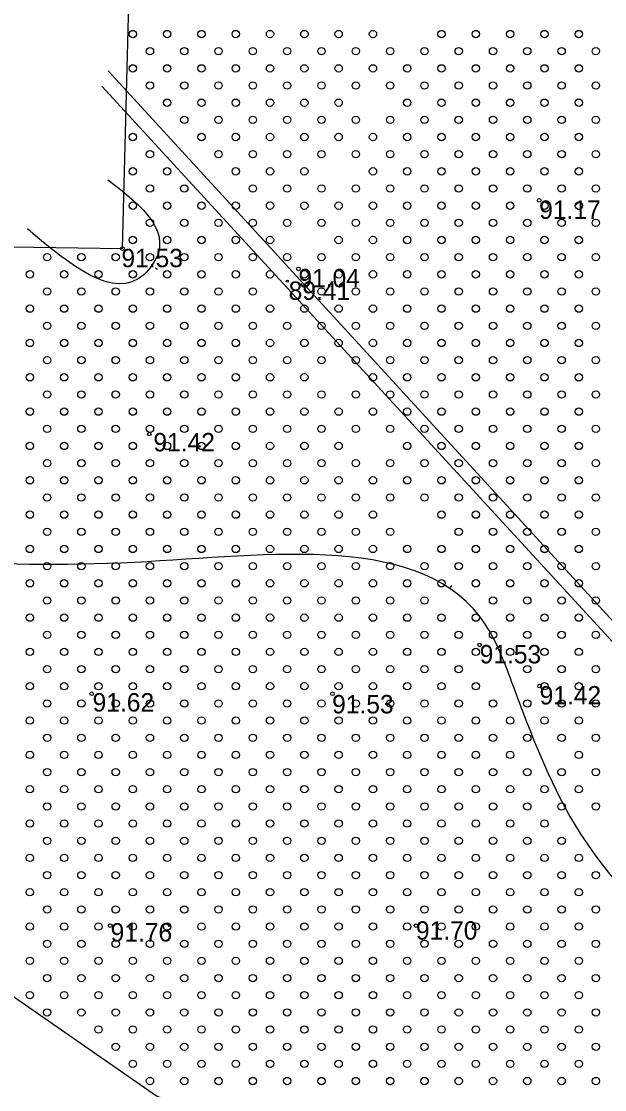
# Model space of a CAD drawing. Extents: x 316000 to 728450, y 314368 to 726000.
# Drawn here: x 725534.2 to 725653.3, y 315232.8 to 315450.6 of the extents above; entities that cross this region are included whole.
import ezdxf

# ---------------------------------------------------------------- set-up
doc = ezdxf.new("R2010")
doc.units = 0
for name, color, linetype in [('HIDG_ELEM_####_####_#', 7, 'Continuous'), ('HIDG_GRAV_####_####_#', 7, 'Continuous'), ('RAMI_UZMR_####_####_#', 7, 'Continuous'), ('RELJ_AATZ_####_TKST_#', 7, 'Continuous'), ('RELJ_ELEM_####_####_#', 7, 'Continuous'), ('RELJ_HORZ_PAMT_####_#', 7, 'Continuous'), ('TERT_ELEM_####_####_#', 7, 'Continuous')]:
    doc.layers.add(name, color=color, linetype=linetype)

msp = doc.modelspace()

# ---------------------------------------------------------------- linework, layer by layer
at = {"layer": 'HIDG_ELEM_####_####_#'}
msp.add_circle((725588.54, 315397.6), 0.225, dxfattribs=at)
at = {"layer": 'HIDG_GRAV_####_####_#'}
for points in [[(725655.9, 315327.28), (725551.95, 315440.48)], [(725550.64, 315437.37), (725654.91, 315324.09), (725793.17, 315176.93), (726030.02, 314925.45), (726035.1, 314929.94), (725796.17, 315178.83)]]:
    msp.add_lwpolyline(points, dxfattribs=at)
at = {"layer": 'RAMI_UZMR_####_####_#'}
msp.add_lwpolyline([(727254.69, 315085.95), (727002.7, 315002.84), (726508.21, 314868.03), (726416.7, 314837.05), (725982.38, 314530.96), (725916.44, 314513.26), (725799.16, 314549.2), (725735.9, 314623.63), (725701.82, 314711.1), (725697.25, 315112.64), (725659.91, 315163.35), (725614.81, 315211.65), (725561.8, 315231.45), (725500.09, 315274.21), (725474.77, 315308.26), (725484.26, 315374.77), (725505.03, 315405.04), (725554.87, 315404.25), (725559.14, 315567.14), (725558.67, 315591.68), (725662, 315676.73), (726089.69, 315915.19)], dxfattribs=at)
at = {"layer": 'RELJ_ELEM_####_####_#'}
for centre in [(725639.93, 315414.06), (725554.87, 315404.25), (725590.78, 315400.1), (725560.36, 315366.44), (725627.78, 315323.42), (725640.01, 315315.04), (725548.6, 315313.48), (725597.73, 315313.48), (725552.38, 315266.19), (725614.81, 315266.19)]:
    msp.add_circle(centre, 0.375, dxfattribs=at)
at = {"layer": 'RELJ_HORZ_PAMT_####_#'}
for p, q in [((725562.06, 315399.96), (725561.65, 315400.24)), ((725622.03, 315335.52), (725621.74, 315335.11))]:
    msp.add_line(p, q, dxfattribs=at)
for points in [[(725551.91, 315418.27), (725562.22, 315403.55), (725559.23, 315398.92), (725535.49, 315408.26)], [(726081.57, 315247.05), (726057.5, 315241.5), (726036.5, 315213.5), (725977, 315161), (725966.5, 315108.5), (725903.5, 315045.5), (725862.12, 315076.6), (725805.5, 315130), (725759.7, 315178.88), (725709.89, 315228.8), (725646.99, 315287.19), (725634.68, 315314.96), (725629.04, 315327.48), (725557.35, 315340.26), (725478.3, 315344.16)]]:
    msp.add_spline(points, degree=3, dxfattribs=at)
at = {"layer": 'TERT_ELEM_####_####_#'}
for centre in [(725557, 315448), (725564, 315448), (725571, 315448), (725578, 315448), (725585, 315448), (725592, 315448), (725599, 315448), (725606, 315448), (725620, 315448), (725627, 315448), (725634, 315448), (725641, 315448), (725648, 315448), (725560.5, 315444.5), (725567.5, 315444.5), (725574.5, 315444.5), (725581.5, 315444.5), (725588.5, 315444.5), (725595.5, 315444.5), (725602.5, 315444.5), (725609.5, 315444.5), (725616.5, 315444.5), (725623.5, 315444.5), (725630.5, 315444.5), (725637.5, 315444.5), (725644.5, 315444.5), (725651.5, 315444.5), (725557, 315441), (725564, 315441), (725571, 315441), (725578, 315441), (725585, 315441), (725592, 315441), (725599, 315441), (725606, 315441), (725613, 315441), (725620, 315441), (725627, 315441), (725634, 315441), (725641, 315441), (725648, 315441), (725560.5, 315437.5), (725567.5, 315437.5), (725574.5, 315437.5), (725581.5, 315437.5), (725588.5, 315437.5), (725595.5, 315437.5), (725602.5, 315437.5), (725609.5, 315437.5), (725616.5, 315437.5), (725623.5, 315437.5), (725630.5, 315437.5), (725637.5, 315437.5), (725644.5, 315437.5), (725651.5, 315437.5), (725564, 315434), (725571, 315434), (725578, 315434), (725585, 315434), (725592, 315434), (725599, 315434), (725613, 315434), (725620, 315434), (725627, 315434), (725634, 315434), (725641, 315434), (725648, 315434), (725567.5, 315430.5), (725574.5, 315430.5), (725581.5, 315430.5), (725588.5, 315430.5), (725595.5, 315430.5), (725602.5, 315430.5), (725609.5, 315430.5), (725616.5, 315430.5), (725623.5, 315430.5), (725630.5, 315430.5), (725637.5, 315430.5), (725644.5, 315430.5), (725651.5, 315430.5), (725557, 315427), (725571, 315427), (725578, 315427), (725585, 315427), (725592, 315427), (725599, 315427), (725606, 315427), (725613, 315427), (725620, 315427), (725627, 315427), (725634, 315427), (725641, 315427), (725648, 315427), (725560.5, 315423.5), (725574.5, 315423.5), (725581.5, 315423.5), (725588.5, 315423.5), (725595.5, 315423.5), (725602.5, 315423.5), (725609.5, 315423.5), (725616.5, 315423.5), (725623.5, 315423.5), (725630.5, 315423.5), (725637.5, 315423.5), (725644.5, 315423.5), (725651.5, 315423.5), (725557, 315420), (725564, 315420), (725578, 315420), (725585, 315420), (725592, 315420), (725606, 315420), (725613, 315420), (725620, 315420), (725627, 315420), (725634, 315420), (725641, 315420), (725648, 315420), (725560.5, 315416.5), (725567.5, 315416.5), (725581.5, 315416.5), (725588.5, 315416.5), (725595.5, 315416.5), (725602.5, 315416.5), (725609.5, 315416.5), (725616.5, 315416.5), (725623.5, 315416.5), (725630.5, 315416.5), (725637.5, 315416.5), (725644.5, 315416.5), (725651.5, 315416.5), (725557, 315413), (725564, 315413), (725571, 315413), (725578, 315413), (725585, 315413), (725592, 315413), (725599, 315413), (725606, 315413), (725613, 315413), (725620, 315413), (725627, 315413), (725634, 315413), (725641, 315413), (725648, 315413), (725560.5, 315409.5), (725567.5, 315409.5), (725574.5, 315409.5), (725581.5, 315409.5), (725588.5, 315409.5), (725595.5, 315409.5), (725602.5, 315409.5), (725609.5, 315409.5), (725616.5, 315409.5), (725623.5, 315409.5), (725630.5, 315409.5), (725637.5, 315409.5), (725644.5, 315409.5), (725651.5, 315409.5), (725557, 315406), (725564, 315406), (725571, 315406), (725578, 315406), (725585, 315406), (725599, 315406), (725606, 315406), (725613, 315406), (725620, 315406), (725627, 315406), (725634, 315406), (725641, 315406), (725648, 315406), (725539.5, 315402.5), (725546.5, 315402.5), (725553.5, 315402.5), (725560.5, 315402.5), (725567.5, 315402.5), (725574.5, 315402.5), (725581.5, 315402.5), (725588.5, 315402.5), (725595.5, 315402.5), (725602.5, 315402.5), (725609.5, 315402.5), (725616.5, 315402.5), (725623.5, 315402.5), (725630.5, 315402.5), (725637.5, 315402.5), (725644.5, 315402.5), (725651.5, 315402.5), (725536, 315399), (725543, 315399), (725550, 315399), (725557, 315399), (725564, 315399), (725571, 315399), (725578, 315399), (725585, 315399), (725592, 315399), (725599, 315399), (725606, 315399), (725613, 315399), (725620, 315399), (725627, 315399), (725634, 315399), (725641, 315399), (725648, 315399), (725539.5, 315395.5), (725546.5, 315395.5), (725553.5, 315395.5), (725560.5, 315395.5), (725567.5, 315395.5), (725574.5, 315395.5), (725581.5, 315395.5), (725595.5, 315395.5), (725602.5, 315395.5), (725609.5, 315395.5), (725616.5, 315395.5), (725623.5, 315395.5), (725630.5, 315395.5), (725637.5, 315395.5), (725644.5, 315395.5), (725651.5, 315395.5), (725536, 315392), (725543, 315392), (725550, 315392), (725557, 315392), (725564, 315392), (725571, 315392), (725578, 315392), (725585, 315392), (725592, 315392), (725599, 315392), (725606, 315392), (725613, 315392), (725620, 315392), (725627, 315392), (725634, 315392), (725641, 315392), (725648, 315392), (725539.5, 315388.5), (725546.5, 315388.5), (725553.5, 315388.5), (725560.5, 315388.5), (725567.5, 315388.5), (725574.5, 315388.5), (725581.5, 315388.5), (725588.5, 315388.5), (725595.5, 315388.5), (725602.5, 315388.5), (725609.5, 315388.5), (725616.5, 315388.5), (725623.5, 315388.5), (725630.5, 315388.5), (725637.5, 315388.5), (725644.5, 315388.5), (725651.5, 315388.5), (725536, 315385), (725543, 315385), (725550, 315385), (725557, 315385), (725564, 315385), (725571, 315385), (725578, 315385), (725585, 315385), (725592, 315385), (725599, 315385), (725606, 315385), (725613, 315385), (725620, 315385), (725627, 315385), (725634, 315385), (725641, 315385), (725648, 315385), (725539.5, 315381.5), (725546.5, 315381.5), (725553.5, 315381.5), (725560.5, 315381.5), (725567.5, 315381.5), (725574.5, 315381.5), (725581.5, 315381.5), (725588.5, 315381.5), (725595.5, 315381.5), (725602.5, 315381.5), (725609.5, 315381.5), (725616.5, 315381.5), (725623.5, 315381.5), (725630.5, 315381.5), (725637.5, 315381.5), (725644.5, 315381.5), (725651.5, 315381.5), (725536, 315378), (725543, 315378), (725550, 315378), (725557, 315378), (725564, 315378), (725571, 315378), (725578, 315378), (725585, 315378), (725592, 315378), (725606, 315378), (725613, 315378), (725620, 315378), (725627, 315378), (725634, 315378), (725641, 315378), (725648, 315378), (725539.5, 315374.5), (725546.5, 315374.5), (725553.5, 315374.5), (725560.5, 315374.5), (725567.5, 315374.5), (725574.5, 315374.5), (725581.5, 315374.5), (725588.5, 315374.5), (725595.5, 315374.5), (725602.5, 315374.5), (725609.5, 315374.5), (725616.5, 315374.5), (725623.5, 315374.5), (725630.5, 315374.5), (725637.5, 315374.5), (725644.5, 315374.5), (725651.5, 315374.5), (725536, 315371), (725543, 315371), (725550, 315371), (725557, 315371), (725564, 315371), (725571, 315371), (725578, 315371), (725585, 315371), (725592, 315371), (725599, 315371), (725606, 315371), (725613, 315371), (725620, 315371), (725627, 315371), (725634, 315371), (725641, 315371), (725648, 315371), (725539.5, 315367.5), (725546.5, 315367.5), (725553.5, 315367.5), (725560.5, 315367.5), (725567.5, 315367.5), (725574.5, 315367.5), (725581.5, 315367.5), (725588.5, 315367.5), (725595.5, 315367.5), (725602.5, 315367.5), (725609.5, 315367.5), (725616.5, 315367.5), (725623.5, 315367.5), (725630.5, 315367.5), (725637.5, 315367.5), (725644.5, 315367.5), (725651.5, 315367.5), (725536, 315364), (725543, 315364), (725550, 315364), (725557, 315364), (725564, 315364), (725571, 315364), (725578, 315364), (725585, 315364), (725592, 315364), (725599, 315364), (725613, 315364), (725620, 315364), (725627, 315364), (725634, 315364), (725641, 315364), (725648, 315364), (725539.5, 315360.5), (725546.5, 315360.5), (725553.5, 315360.5), (725560.5, 315360.5), (725567.5, 315360.5), (725574.5, 315360.5), (725581.5, 315360.5), (725588.5, 315360.5), (725595.5, 315360.5), (725602.5, 315360.5), (725609.5, 315360.5), (725616.5, 315360.5), (725623.5, 315360.5), (725630.5, 315360.5), (725637.5, 315360.5), (725644.5, 315360.5), (725651.5, 315360.5), (725536, 315357), (725543, 315357), (725550, 315357), (725557, 315357), (725564, 315357), (725571, 315357), (725578, 315357), (725585, 315357), (725592, 315357), (725599, 315357), (725606, 315357), (725613, 315357), (725620, 315357), (725627, 315357), (725634, 315357), (725641, 315357), (725648, 315357), (725539.5, 315353.5), (725546.5, 315353.5), (725553.5, 315353.5), (725560.5, 315353.5), (725567.5, 315353.5), (725574.5, 315353.5), (725581.5, 315353.5), (725588.5, 315353.5), (725595.5, 315353.5), (725602.5, 315353.5), (725609.5, 315353.5), (725616.5, 315353.5), (725623.5, 315353.5), (725630.5, 315353.5), (725637.5, 315353.5), (725644.5, 315353.5), (725651.5, 315353.5), (725536, 315350), (725543, 315350), (725550, 315350), (725557, 315350), (725564, 315350), (725571, 315350), (725578, 315350), (725585, 315350), (725592, 315350), (725599, 315350), (725606, 315350), (725620, 315350), (725627, 315350), (725634, 315350), (725641, 315350), (725648, 315350), (725539.5, 315346.5), (725546.5, 315346.5), (725553.5, 315346.5), (725560.5, 315346.5), (725567.5, 315346.5), (725574.5, 315346.5), (725581.5, 315346.5), (725588.5, 315346.5), (725595.5, 315346.5), (725602.5, 315346.5), (725609.5, 315346.5), (725623.5, 315346.5), (725630.5, 315346.5), (725637.5, 315346.5), (725644.5, 315346.5), (725651.5, 315346.5), (725536, 315343), (725543, 315343), (725550, 315343), (725557, 315343), (725564, 315343), (725571, 315343), (725578, 315343), (725585, 315343), (725592, 315343), (725599, 315343), (725606, 315343), (725613, 315343), (725620, 315343), (725627, 315343), (725634, 315343), (725641, 315343), (725648, 315343), (725539.5, 315339.5), (725546.5, 315339.5), (725553.5, 315339.5), (725560.5, 315339.5), (725567.5, 315339.5), (725574.5, 315339.5), (725581.5, 315339.5), (725588.5, 315339.5), (725595.5, 315339.5), (725602.5, 315339.5), (725609.5, 315339.5), (725616.5, 315339.5), (725623.5, 315339.5), (725630.5, 315339.5), (725637.5, 315339.5), (725644.5, 315339.5), (725651.5, 315339.5), (725536, 315336), (725543, 315336), (725550, 315336), (725557, 315336), (725564, 315336), (725571, 315336), (725578, 315336), (725585, 315336), (725592, 315336), (725599, 315336), (725606, 315336), (725613, 315336), (725620, 315336), (725627, 315336), (725634, 315336), (725641, 315336), (725648, 315336), (725539.5, 315332.5), (725546.5, 315332.5), (725553.5, 315332.5), (725560.5, 315332.5), (725567.5, 315332.5), (725574.5, 315332.5), (725581.5, 315332.5), (725588.5, 315332.5), (725595.5, 315332.5), (725602.5, 315332.5), (725609.5, 315332.5), (725616.5, 315332.5), (725630.5, 315332.5), (725637.5, 315332.5), (725644.5, 315332.5), (725651.5, 315332.5), (725536, 315329), (725543, 315329), (725550, 315329), (725557, 315329), (725564, 315329), (725571, 315329), (725578, 315329), (725585, 315329), (725592, 315329), (725599, 315329), (725606, 315329), (725613, 315329), (725620, 315329), (725627, 315329), (725634, 315329), (725641, 315329), (725648, 315329), (725539.5, 315325.5), (725546.5, 315325.5), (725553.5, 315325.5), (725560.5, 315325.5), (725567.5, 315325.5), (725574.5, 315325.5), (725581.5, 315325.5), (725588.5, 315325.5), (725595.5, 315325.5), (725602.5, 315325.5), (725609.5, 315325.5), (725616.5, 315325.5), (725623.5, 315325.5), (725630.5, 315325.5), (725637.5, 315325.5), (725644.5, 315325.5), (725651.5, 315325.5), (725536, 315322), (725543, 315322), (725550, 315322), (725557, 315322), (725564, 315322), (725571, 315322), (725578, 315322), (725585, 315322), (725592, 315322), (725599, 315322), (725606, 315322), (725613, 315322), (725620, 315322), (725627, 315322), (725634, 315322), (725641, 315322), (725648, 315322), (725539.5, 315318.5), (725546.5, 315318.5), (725553.5, 315318.5), (725560.5, 315318.5), (725567.5, 315318.5), (725574.5, 315318.5), (725581.5, 315318.5), (725588.5, 315318.5), (725595.5, 315318.5), (725602.5, 315318.5), (725609.5, 315318.5), (725616.5, 315318.5), (725623.5, 315318.5), (725637.5, 315318.5), (725644.5, 315318.5), (725651.5, 315318.5), (725536, 315315), (725543, 315315), (725550, 315315), (725557, 315315), (725564, 315315), (725571, 315315), (725578, 315315), (725585, 315315), (725592, 315315), (725599, 315315), (725606, 315315), (725613, 315315), (725620, 315315), (725627, 315315), (725641, 315315), (725648, 315315), (725539.5, 315311.5), (725546.5, 315311.5), (725553.5, 315311.5), (725560.5, 315311.5), (725567.5, 315311.5), (725574.5, 315311.5), (725581.5, 315311.5), (725588.5, 315311.5), (725595.5, 315311.5), (725602.5, 315311.5), (725609.5, 315311.5), (725616.5, 315311.5), (725623.5, 315311.5), (725630.5, 315311.5), (725637.5, 315311.5), (725644.5, 315311.5), (725651.5, 315311.5), (725536, 315308), (725543, 315308), (725550, 315308), (725557, 315308), (725564, 315308), (725571, 315308), (725578, 315308), (725585, 315308), (725592, 315308), (725599, 315308), (725606, 315308), (725613, 315308), (725620, 315308), (725627, 315308), (725634, 315308), (725641, 315308), (725648, 315308), (725539.5, 315304.5), (725546.5, 315304.5), (725553.5, 315304.5), (725560.5, 315304.5), (725567.5, 315304.5), (725574.5, 315304.5), (725581.5, 315304.5), (725588.5, 315304.5), (725595.5, 315304.5), (725602.5, 315304.5), (725609.5, 315304.5), (725616.5, 315304.5), (725623.5, 315304.5), (725630.5, 315304.5), (725637.5, 315304.5), (725644.5, 315304.5), (725651.5, 315304.5), (725536, 315301), (725543, 315301), (725550, 315301), (725557, 315301), (725564, 315301), (725571, 315301), (725578, 315301), (725585, 315301), (725592, 315301), (725599, 315301), (725606, 315301), (725613, 315301), (725620, 315301), (725627, 315301), (725634, 315301), (725648, 315301), (725539.5, 315297.5), (725546.5, 315297.5), (725553.5, 315297.5), (725560.5, 315297.5), (725567.5, 315297.5), (725574.5, 315297.5), (725581.5, 315297.5), (725588.5, 315297.5), (725595.5, 315297.5), (725602.5, 315297.5), (725609.5, 315297.5), (725616.5, 315297.5), (725623.5, 315297.5), (725630.5, 315297.5), (725637.5, 315297.5), (725644.5, 315297.5), (725651.5, 315297.5), (725536, 315294), (725543, 315294), (725550, 315294), (725557, 315294), (725564, 315294), (725571, 315294), (725578, 315294), (725585, 315294), (725592, 315294), (725599, 315294), (725606, 315294), (725613, 315294), (725620, 315294), (725627, 315294), (725634, 315294), (725641, 315294), (725648, 315294), (725539.5, 315290.5), (725546.5, 315290.5), (725553.5, 315290.5), (725560.5, 315290.5), (725567.5, 315290.5), (725574.5, 315290.5), (725581.5, 315290.5), (725588.5, 315290.5), (725595.5, 315290.5), (725602.5, 315290.5), (725609.5, 315290.5), (725616.5, 315290.5), (725623.5, 315290.5), (725630.5, 315290.5), (725637.5, 315290.5), (725644.5, 315290.5), (725651.5, 315290.5), (725536, 315287), (725543, 315287), (725550, 315287), (725557, 315287), (725564, 315287), (725571, 315287), (725578, 315287), (725585, 315287), (725592, 315287), (725599, 315287), (725606, 315287), (725613, 315287), (725620, 315287), (725627, 315287), (725634, 315287), (725641, 315287), (725539.5, 315283.5), (725546.5, 315283.5), (725553.5, 315283.5), (725560.5, 315283.5), (725567.5, 315283.5), (725574.5, 315283.5), (725581.5, 315283.5), (725588.5, 315283.5), (725595.5, 315283.5), (725602.5, 315283.5), (725609.5, 315283.5), (725616.5, 315283.5), (725623.5, 315283.5), (725630.5, 315283.5), (725637.5, 315283.5), (725644.5, 315283.5), (725536, 315280), (725543, 315280), (725550, 315280), (725557, 315280), (725564, 315280), (725571, 315280), (725578, 315280), (725585, 315280), (725592, 315280), (725599, 315280), (725606, 315280), (725613, 315280), (725620, 315280), (725627, 315280), (725634, 315280), (725641, 315280), (725648, 315280), (725539.5, 315276.5), (725546.5, 315276.5), (725553.5, 315276.5), (725560.5, 315276.5), (725567.5, 315276.5), (725574.5, 315276.5), (725581.5, 315276.5), (725588.5, 315276.5), (725595.5, 315276.5), (725602.5, 315276.5), (725609.5, 315276.5), (725616.5, 315276.5), (725623.5, 315276.5), (725630.5, 315276.5), (725637.5, 315276.5), (725644.5, 315276.5), (725651.5, 315276.5), (725536, 315273), (725543, 315273), (725550, 315273), (725557, 315273), (725564, 315273), (725571, 315273), (725578, 315273), (725585, 315273), (725592, 315273), (725599, 315273), (725606, 315273), (725613, 315273), (725620, 315273), (725627, 315273), (725634, 315273), (725641, 315273), (725648, 315273), (725539.5, 315269.5), (725546.5, 315269.5), (725553.5, 315269.5), (725560.5, 315269.5), (725567.5, 315269.5), (725574.5, 315269.5), (725581.5, 315269.5), (725588.5, 315269.5), (725595.5, 315269.5), (725602.5, 315269.5), (725609.5, 315269.5), (725616.5, 315269.5), (725623.5, 315269.5), (725630.5, 315269.5), (725637.5, 315269.5), (725644.5, 315269.5), (725651.5, 315269.5), (725536, 315266), (725543, 315266), (725550, 315266), (725557, 315266), (725564, 315266), (725571, 315266), (725578, 315266), (725585, 315266), (725592, 315266), (725599, 315266), (725606, 315266), (725613, 315266), (725620, 315266), (725627, 315266), (725634, 315266), (725641, 315266), (725648, 315266), (725539.5, 315262.5), (725546.5, 315262.5), (725553.5, 315262.5), (725560.5, 315262.5), (725567.5, 315262.5), (725574.5, 315262.5), (725581.5, 315262.5), (725588.5, 315262.5), (725595.5, 315262.5), (725602.5, 315262.5), (725609.5, 315262.5), (725616.5, 315262.5), (725623.5, 315262.5), (725630.5, 315262.5), (725637.5, 315262.5), (725644.5, 315262.5), (725651.5, 315262.5), (725536, 315259), (725543, 315259), (725550, 315259), (725557, 315259), (725564, 315259), (725571, 315259), (725578, 315259), (725585, 315259), (725592, 315259), (725599, 315259), (725606, 315259), (725613, 315259), (725620, 315259), (725627, 315259), (725634, 315259), (725641, 315259), (725648, 315259), (725539.5, 315255.5), (725546.5, 315255.5), (725553.5, 315255.5), (725560.5, 315255.5), (725567.5, 315255.5), (725574.5, 315255.5), (725581.5, 315255.5), (725588.5, 315255.5), (725595.5, 315255.5), (725602.5, 315255.5), (725609.5, 315255.5), (725616.5, 315255.5), (725623.5, 315255.5), (725630.5, 315255.5), (725637.5, 315255.5), (725644.5, 315255.5), (725651.5, 315255.5), (725536, 315252), (725543, 315252), (725550, 315252), (725557, 315252), (725564, 315252), (725571, 315252), (725578, 315252), (725585, 315252), (725592, 315252), (725599, 315252), (725606, 315252), (725613, 315252), (725620, 315252), (725627, 315252), (725634, 315252), (725641, 315252), (725648, 315252), (725539.5, 315248.5), (725546.5, 315248.5), (725553.5, 315248.5), (725560.5, 315248.5), (725567.5, 315248.5), (725574.5, 315248.5), (725581.5, 315248.5), (725588.5, 315248.5), (725595.5, 315248.5), (725602.5, 315248.5), (725609.5, 315248.5), (725616.5, 315248.5), (725623.5, 315248.5), (725630.5, 315248.5), (725637.5, 315248.5), (725644.5, 315248.5), (725651.5, 315248.5), (725550, 315245), (725557, 315245), (725564, 315245), (725571, 315245), (725578, 315245), (725585, 315245), (725592, 315245), (725599, 315245), (725606, 315245), (725613, 315245), (725620, 315245), (725627, 315245), (725634, 315245), (725641, 315245), (725648, 315245), (725553.5, 315241.5), (725560.5, 315241.5), (725567.5, 315241.5), (725574.5, 315241.5), (725581.5, 315241.5), (725588.5, 315241.5), (725595.5, 315241.5), (725602.5, 315241.5), (725609.5, 315241.5), (725616.5, 315241.5), (725623.5, 315241.5), (725630.5, 315241.5), (725637.5, 315241.5), (725644.5, 315241.5), (725651.5, 315241.5), (725557, 315238), (725564, 315238), (725571, 315238), (725578, 315238), (725585, 315238), (725592, 315238), (725599, 315238), (725606, 315238), (725613, 315238), (725620, 315238), (725627, 315238), (725634, 315238), (725641, 315238), (725648, 315238), (725560.5, 315234.5), (725567.5, 315234.5), (725574.5, 315234.5), (725581.5, 315234.5), (725588.5, 315234.5), (725595.5, 315234.5), (725602.5, 315234.5), (725609.5, 315234.5), (725616.5, 315234.5), (725623.5, 315234.5), (725630.5, 315234.5), (725637.5, 315234.5), (725644.5, 315234.5), (725651.5, 315234.5)]:
    msp.add_circle(centre, 0.75, dxfattribs=at)

# ---------------------------------------------------------------- texts
at = {"layer": 'RELJ_AATZ_####_TKST_#'}
for s, p in [('91.17', (725639.93, 315410.31)), ('91.53', (725554.67, 315400.45)), ('91.04', (725590.78, 315396.35)), ('89.41', (725588.8, 315393.79)), ('91.42', (725561.2, 315362.9)), ('91.53', (725627.78, 315319.67)), ('91.42', (725640.01, 315311.29)), ('91.62', (725548.79, 315309.85)), ('91.53', (725597.67, 315309.47)), ('91.76', (725552.47, 315262.95)), ('91.70', (725614.77, 315263.33))]:
    msp.add_text(s, height=3.75, dxfattribs=at).set_placement(p)

doc.saveas('drawing.dxf')
